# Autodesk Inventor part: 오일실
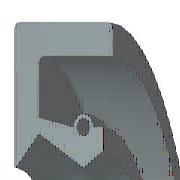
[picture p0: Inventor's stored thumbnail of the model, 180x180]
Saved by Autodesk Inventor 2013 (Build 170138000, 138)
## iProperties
Created: 2009-02
Part Number: 오일실
Material: 고무
Description: 오일-실
Document SubType Name: Modeling
Standard: KS B 2804
Designer: KYOUNG IL JANG
Standards Organization: KS
Language: ko-KR
Size Designation: D - 10 20 7
Categories: <MemberInstance><Categories><Category DisplayName="샤프트 부품" InternalName="7f7aeb1f-a693-4053-b835-cee3144e0d98" Mnemonic="SHFT"><Category DisplayName="실링" Intern
Density: 0.93 g/cm^3
Mass: 1.11329 g
Surface Area: 16.3871 cm^2
Volume: 1.19708 cm^3
Company: 한국ATC센터
IsCustomPart: 0
Author: KYOUNG IL JANG
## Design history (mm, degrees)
revolve "본체" stored, may be unused: angle "d17" = 90 deg
revolve "스프링1" stored, may be unused: angle "d18" = 90 deg
body "Solid1"
sketch "스케치1"
  geometry: L1 (0, 10)-(7, 10); L2 (7, 8.25)-(1.75, 8.25); L3 (1.75, 6.75)-(4.9, 5); L4 (4.9, 5)-(0, 5); L5 (0, 0)-(9.586, 0) reference; L6 (4.9, 5)-(6.3, 5.875); L7 (0, 18)-(0, -3) reference; L8 (-1.941, 0)-(11.507, 0) reference; L9 (4.2, 7.1)-(1.75, 7.59); L10 (1.75, 7.59)-(1.75, 8.25); L11 (0, 10)-(0, 5.088); L12 (4.9, 5)-(0, 5); L13 (1.75, 6.75)-(0.152, 5.028); L14 (7, 10)-(7, 8.25); L15 (5.6, 7.1)-(6.3, 7.1); L16 (6.3, 7.1)-(6.3, 5.875); C1 r 0.455 at (4.9, 7.1); A1 r 0.7 centre (4.9, 7.1) between (5.6, 7.1) and (4.2, 7.1); A2 r 0.088 centre (0.088, 5.088) between (0, 5.088) and (0.152, 5.028); 1 further point
  constraints: 28 end point, 5 horizontal alignment, 5 point on line, 4 point on circle, 4 vertical alignment, 3 centre point, 3 tangent, 2 collinear, 2 horizontal, 2 perpendicular, 1 coincident, 1 parallel
  dimensions: "d0" = 20 diameter of L1 L5 (= SD2); "d1" = 1.75 distance of L1.end L2.start (= SD); "d2" = 0.91 diameter of C1 (= SPDI); "d3" = 1.4 diameter of A1 (= SPDA); "d4" = 10 diameter of L3.end L5 (= NND); "d5" = 13.5 diameter of L3.start L5 (= TKDM); "d7" = 15.18 diameter of L9.end L5 (= TKDM + 0.24 x SWDT); "d8" = 1.75 distance between parallel lines of L11 L10 (= SD); "d9" = 4.9 distance from line of L11 C1.centre (= SPDST); "d10" = 14.2 diameter of C1.centre L5 (= HLDM); "d11" = 0.0875 radius of A2 (= 0.25 x LAB); "d12" = 6.3 distance between parallel lines of L11 L16 (= SDI); "d13" = 11.75 diameter of L6.end L5 (= ABDM); "d14" = 7 distance from line of L11 L1.end (= SWDT)
fillet "모깎기1" dims "d6" = 0.3 (= RR)
other parameters: "SD2" = 20 [user parameter; used in 1 equation term], "SWDT" = 7 [user parameter; used in 2 equation terms], "RR" = 0.3 [user parameter; used in 1 equation term], "SD" = 1.75 [user parameter; used in 2 equation terms], "NND" = 10 [user parameter; used in 1 equation term], "SPDA" = 1.4 [user parameter; used in 1 equation term], "SPDI" = 0.91 [user parameter; used in 1 equation term], "TKDM" = 13.5 [user parameter; used in 2 equation terms], "HLDM" = 14.2 [user parameter; used in 1 equation term], "ABDM" = 11.75 [user parameter; used in 1 equation term], "SDI" = 6.3 [user parameter; used in 1 equation term], "SPDST" = 4.9 [user parameter; used in 1 equation term], "LAB" = 0.35 [user parameter; used in 1 equation term], "d15" = 0, "d16" = 0, "d19" = 0
